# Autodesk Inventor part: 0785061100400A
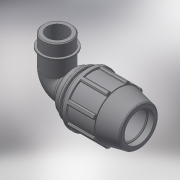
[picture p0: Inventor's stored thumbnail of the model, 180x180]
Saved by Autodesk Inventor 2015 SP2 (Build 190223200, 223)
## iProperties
Created: 2017-02
Part Number: 0785061100400A
Material: Generic
Description: PLASSON 90° ELBOW MALE ADAPTOR 110-4"
Document SubType Name: Modeling
Designer: KIM
Mass: 1366.09 g
Surface Area: 1816.46 cm^2
Volume: 1366.09 cm^3
Density: 1 g/cm^3
Appearance: Default
Author: KIM
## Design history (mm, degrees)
derived "87850.ipt"
feature "Solid1::87850.ipt"
tag "TaggingFeature1"
body "Solid1"
other parameters: "d4" = 22.83333, "d5" = 68.5, "d7" = 181, "d9" = 39.14286, "d11" = 9.13333, "d13" = 120 deg, "d14" = 132, "d15" = 12 deg, "d16" = 157.47, "d18" = 5.5, "d19" = 35 deg, "d20" = 17.5 deg, "d21" = 168.33, "d23" = 0, "d25" = 360 deg, "d27" = 3.62, "d33" = 2.2, "d42" = 101.38, "d43" = 5.43, "d46" = 3.3, "d51" = 274, "d68" = 18.26667, "d73" = 113.03, "d74" = 42, "d75" = 129.9845, "d76" = 79.121, "d77" = 46.2, "d79" = 45.212, "d80" = 3.3909, "d83" = 0, "d84" = 0, "d91" = 135.75, "d93" = 194, "d94" = 113.03, "d95" = 79.121, "d96" = 18.26667, "d97" = 50 deg, "d98" = 4.56667, "d99" = 152.7459, "d100" = 4.56667, "d101" = 4.56667, "d102" = 12.06667, "d103" = 0, "E_" = 181, "A_" = 274, "l_" = 194, "l_2" = 42, "G_" = 113.03
